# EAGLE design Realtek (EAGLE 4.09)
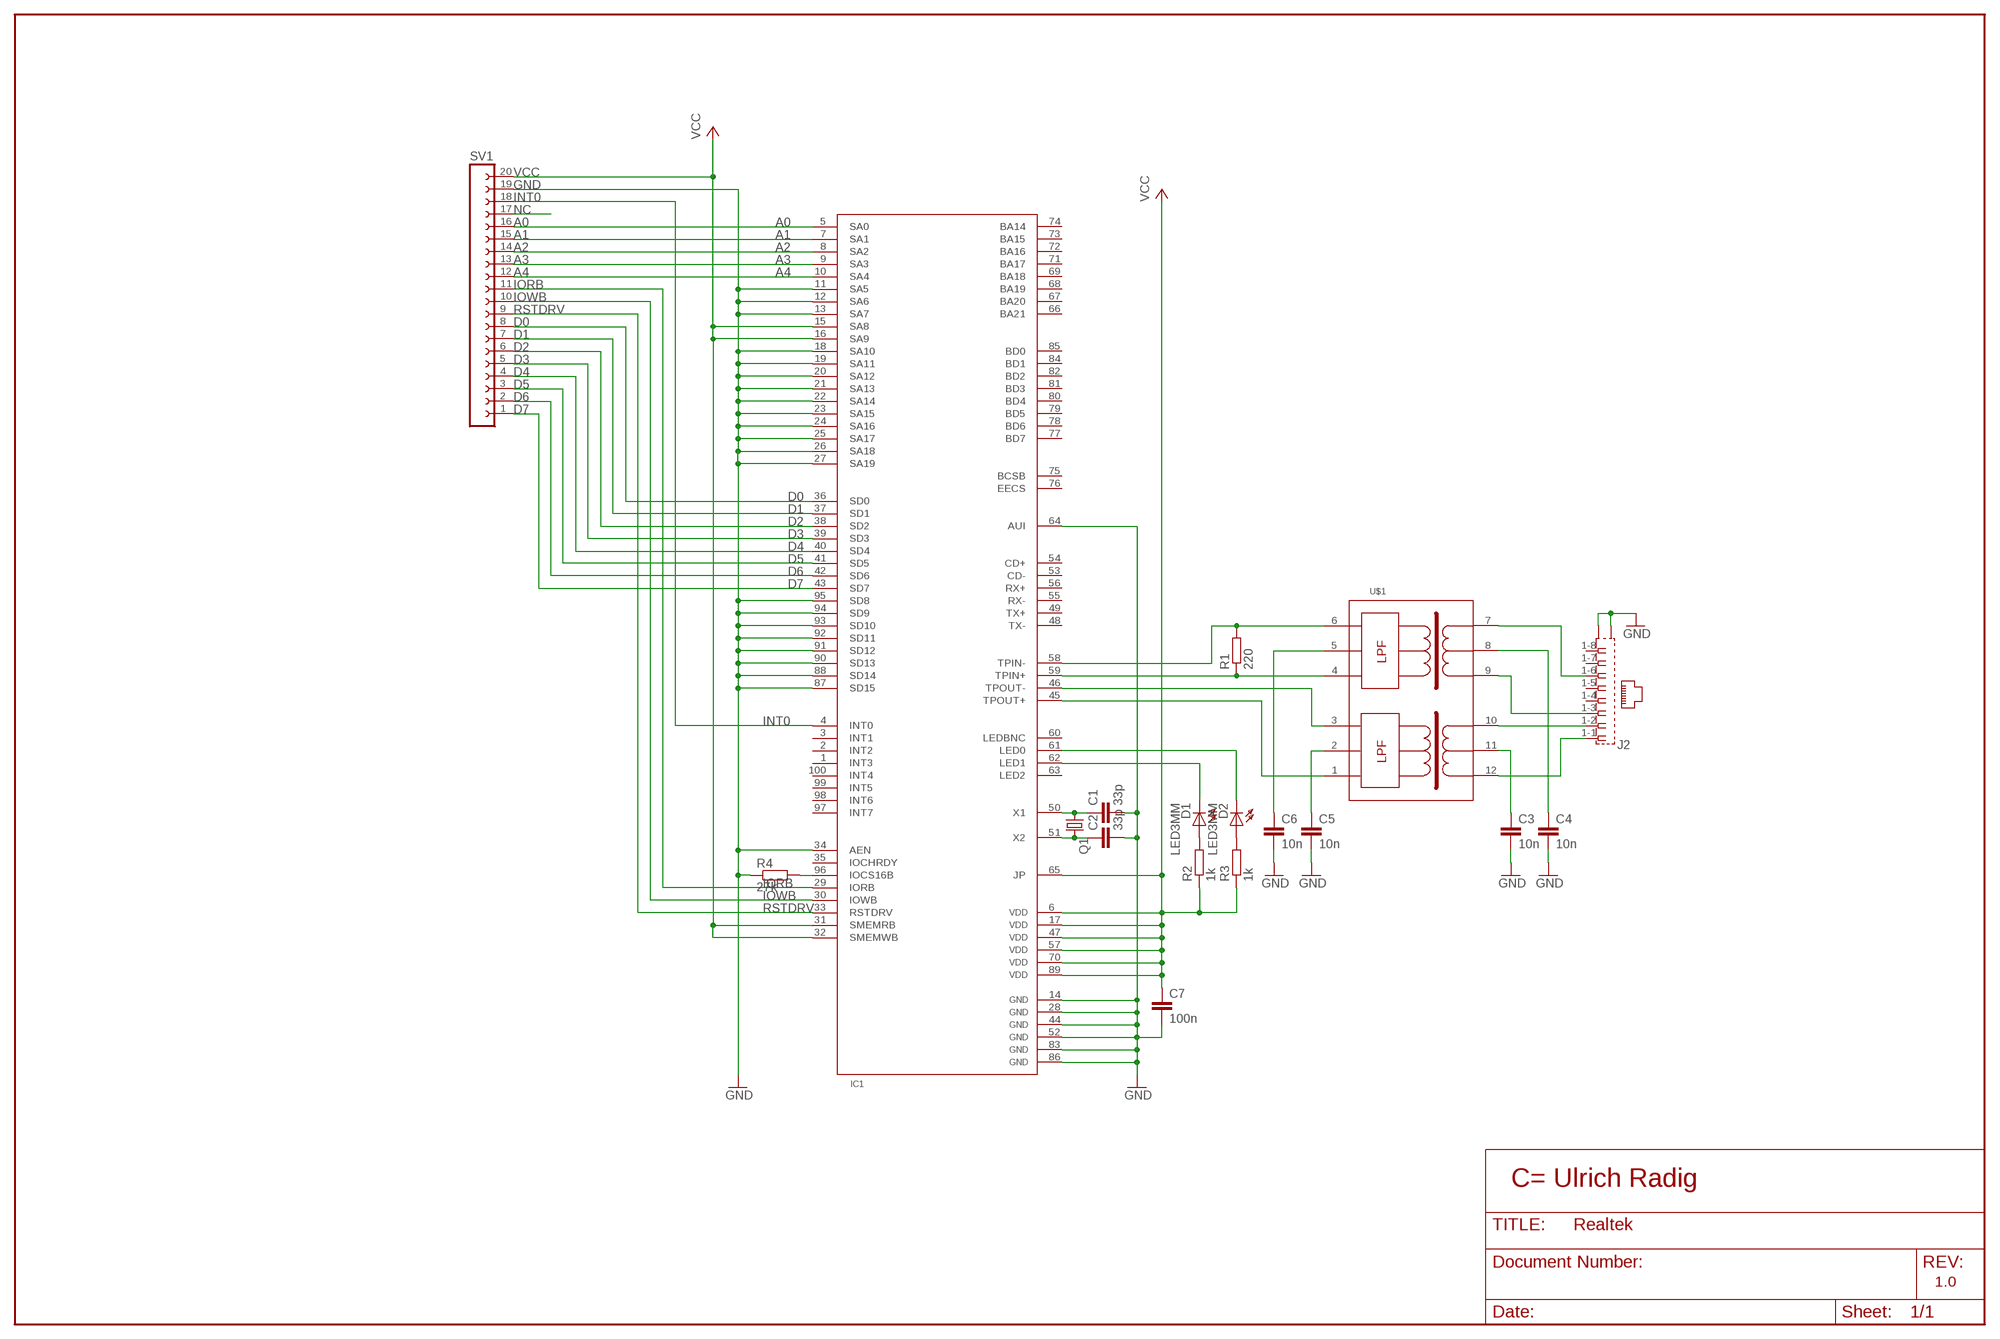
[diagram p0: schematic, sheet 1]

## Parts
C1  33p  C-EUC1206  [C1206]
C2  33p  C-EUC1206  [C1206]
C3  10n  C-EUC1206  [C1206]
C4  10n  C-EUC1206  [C1206]
C5  10n  C-EUC1206  [C1206]
C6  10n  C-EUC1206  [C1206]
C7  100n  C-EUC1206  [C1206]
D1  LED3MM  [LED3MM]
D2  LED3MM  [LED3MM]
IC1  RTL8019  [TQPF100]
J2  557786-1  [557786-1]
Q1  HC49U-H  [HC49U-H]
R1  220  R-EU_R1206  [R1206]
R2  1k  R-EU_M1206  [M1206]
R3  1k  R-EU_M1206  [M1206]
R4  27k  R-EU_M1206  [M1206]
SV1  FE20-1  [FE20]
U$1  20F001  [DIL16/12]

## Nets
A0: IC1.5(SA0) SV1.16
A1: IC1.7(SA1) SV1.15
A2: IC1.8(SA2) SV1.14
A3: IC1.9(SA3) SV1.13
A4: IC1.10(SA4) SV1.12
D0: IC1.36(SD0) SV1.8
D1: IC1.37(SD1) SV1.7
D2: IC1.38(SD2) SV1.6
D3: IC1.39(SD3) SV1.5
D4: IC1.40(SD4) SV1.4
D5: IC1.41(SD5) SV1.3
D6: IC1.42(SD6) SV1.2
D7: IC1.43(SD7) SV1.1
GND: C1.2 C2.2 C3.2 C4.2 C5.2 C6.2 C7.2 IC1.11(SA5) IC1.12(SA6) IC1.13(SA7) IC1.14(G1) IC1.18(SA10) IC1.19(SA11) IC1.20(SA12) IC1.21(SA13) IC1.22(SA14) IC1.23(SA15) IC1.24(SA16) IC1.25(SA17) IC1.26(SA18) IC1.27(SA19) IC1.28(G2) IC1.34(AEN) IC1.44(G3) IC1.52(G4) IC1.64(AUI) IC1.83(G5) IC1.86(G6) IC1.87(SD15) IC1.88(SD14) IC1.90(SD13) IC1.91(SD12) IC1.92(SD11) IC1.93(SD10) IC1.94(SD9) IC1.95(SD8) J2.G1(S2) J2.G2(S1) R4.1 SV1.19
INT0: IC1.4(INT0) SV1.18
IORB: IC1.29(IORB) SV1.11
IOWB: IC1.30(IOWB) SV1.10
N$1: J2.1-1 U$1.12
N$2: J2.1-2 U$1.10
N$3: D2.K(C) IC1.61(LED0)
N$4: D1.K(C) IC1.62(LED1)
N$5: D1.A R2.2
N$6: J2.1-3 U$1.9
N$7: J2.1-6 U$1.7
N$8: IC1.58(TPIN-) R1.2 U$1.6
N$9: IC1.59(TPIN+) R1.1 U$1.4
N$10: IC1.46(TPOUT-) U$1.3
N$11: IC1.45(TPOUT+) U$1.1
N$12: C5.1 U$1.2
N$13: C6.1 U$1.5
N$14: C1.1 IC1.50(X1) Q1.1
N$15: C2.1 IC1.51(X2) Q1.2
N$16: C3.1 U$1.11
N$17: C4.1 U$1.8
N$18: D2.A R3.2
N$31: IC1.96(IOCS16B) R4.2
NC: SV1.17
RSTDRV: IC1.33(RSTDRV) SV1.9
VCC: C7.1 IC1.6(V1) IC1.15(SA8) IC1.16(SA9) IC1.17(V2) IC1.31(SMEMRB) IC1.32(SMEMWB) IC1.47(V3) IC1.57(V4) IC1.65(JP) IC1.70(V5) IC1.89(V6) R2.1 R3.1 SV1.20
Unconnected: IC1.1(INT3) IC1.2(INT2) IC1.3(INT1) IC1.35(IOCHRDY) IC1.48(TX-) IC1.49(TX+) IC1.53(CD-) IC1.54(CD+) IC1.55(RX-) IC1.56(RX+) IC1.60(LEDBNC) IC1.63(LED2) IC1.66(BA21) IC1.67(BA20) IC1.68(BA19) IC1.69(BA18) IC1.71(BA17) IC1.72(BA16) IC1.73(BA15) IC1.74(BA14) IC1.75(BCSB) IC1.76(EECS) IC1.77(BD7) IC1.78(BD6) IC1.79(BD5) IC1.80(BD4) IC1.81(BD3) IC1.82(BD2) IC1.84(BD1) IC1.85(BD0) IC1.97(INT7) IC1.98(INT6) IC1.99(INT5) IC1.100(INT4) J2.1-4 J2.1-5 J2.1-7 J2.1-8

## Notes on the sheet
- C= Ulrich Radig
- 1.0

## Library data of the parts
C1-C7 = rcl:C-EU: CAPACITOR, European symbol
D1 D2 = led:LED3MM: LED
IC1 = Realtek:RTL8019
J2 = con-amp:557786-1: AMP CONNECTOR
Q1 = crystal:HC49U-H: CRYSTAL
R1-R4 = rcl:R-EU_: RESISTOR, European symbol
SV1 = con-lsta:FE20-1: FEMALE HEADER
U$1 = Realtek:20F001

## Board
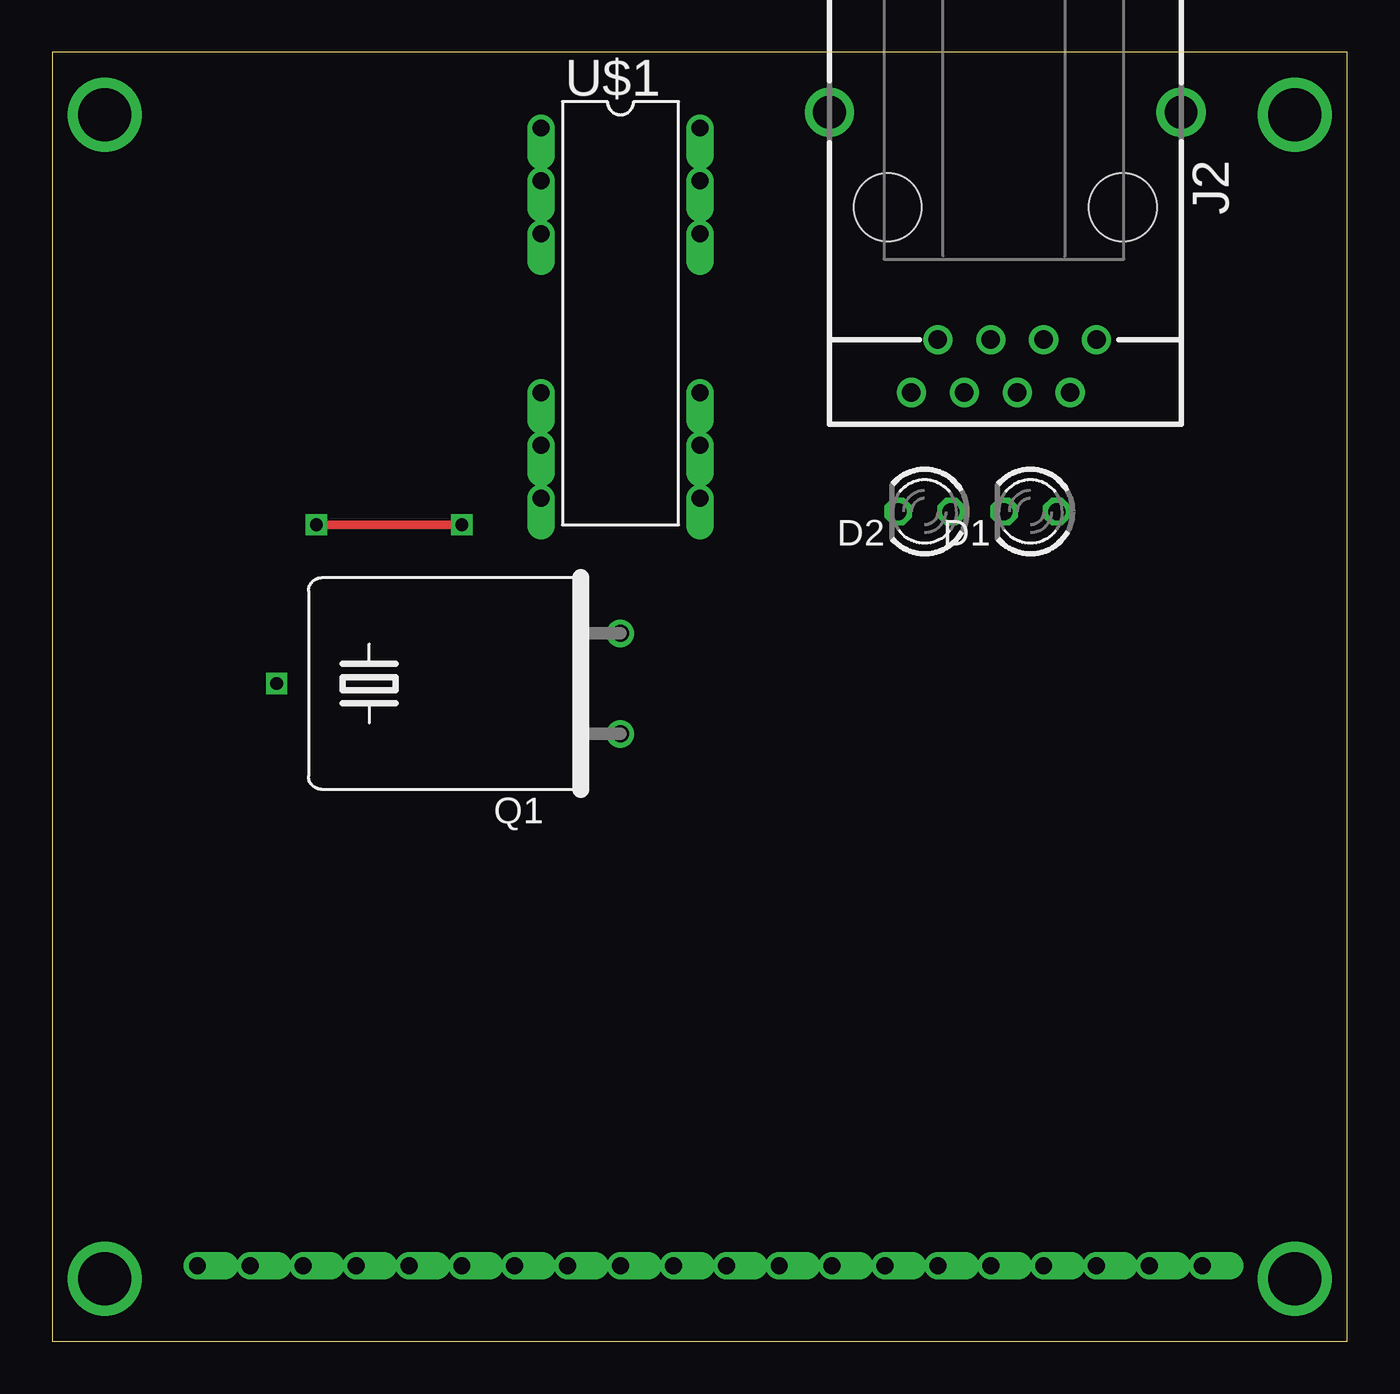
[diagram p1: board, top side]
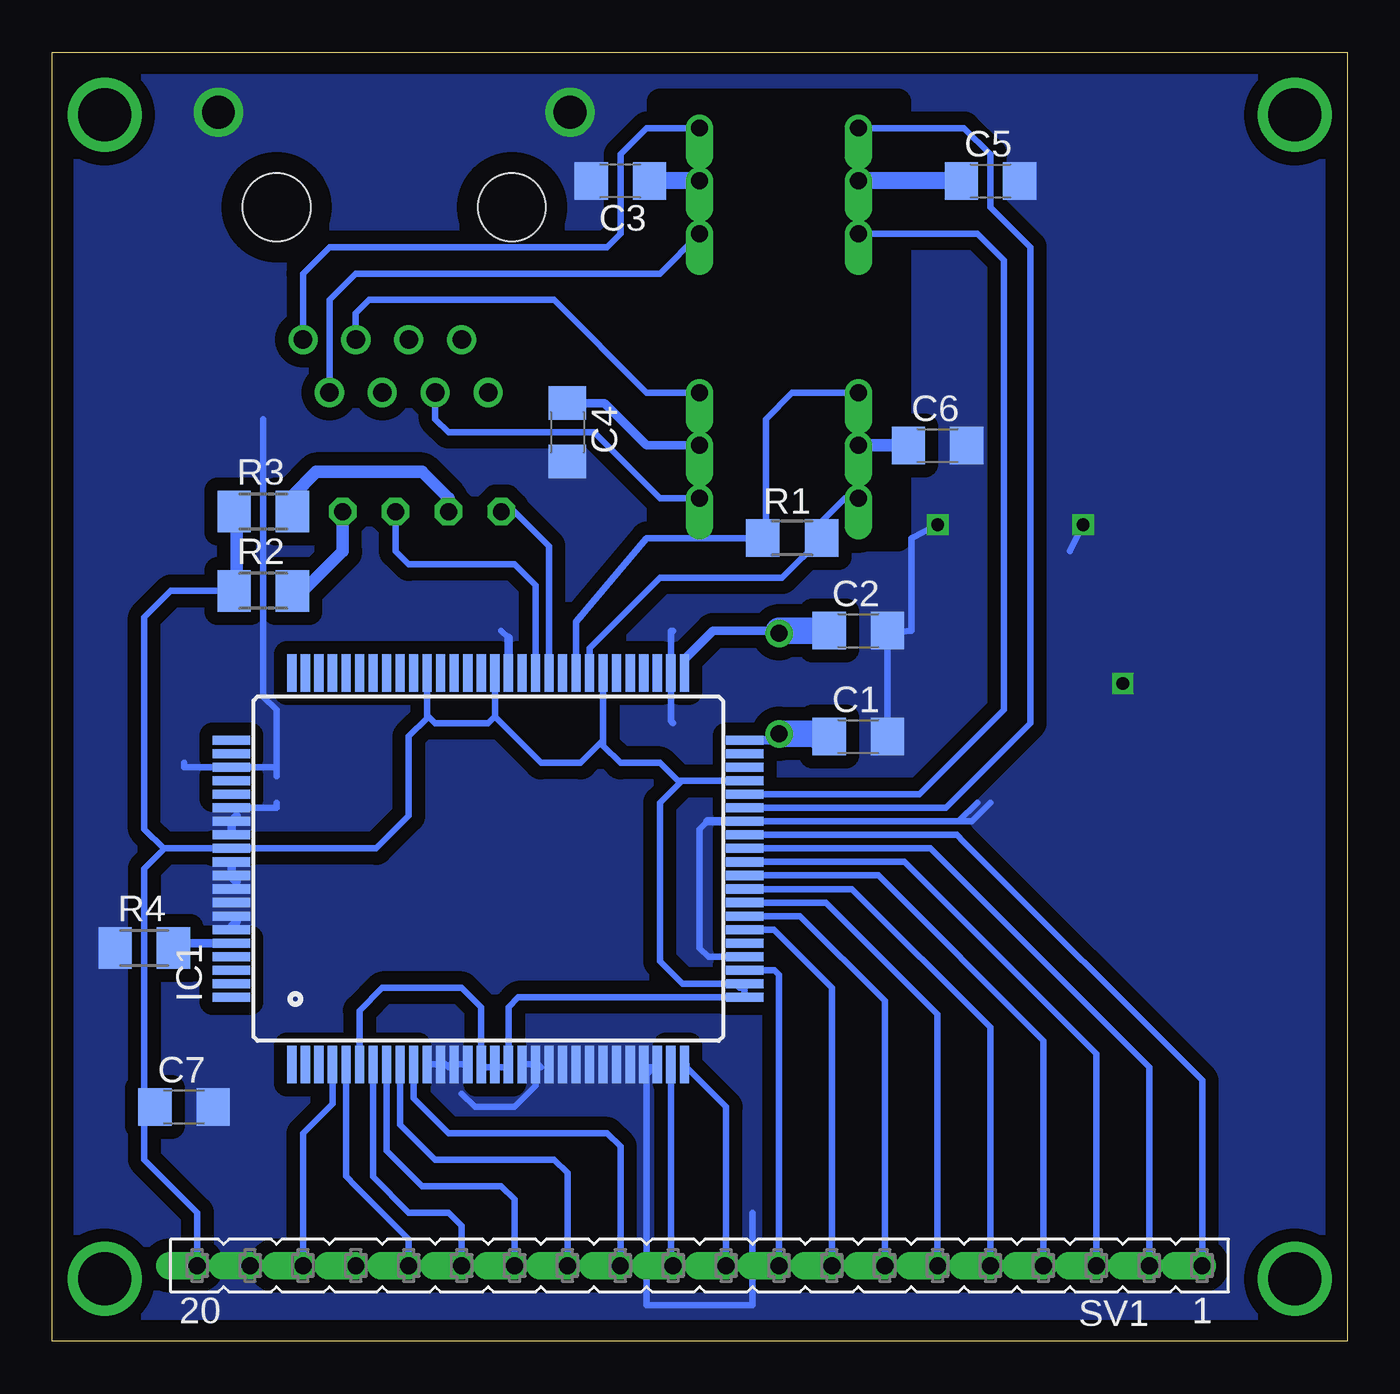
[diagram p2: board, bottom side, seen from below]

Size 62.21 x 61.9 mm. Coordinates in mm from the lower left corner, seen from the top.
Outline: 0,0 62.21,0 62.21,61.9 0,61.9 0,0
Copper layers used: Top, Bottom
bRestrict: area 21.6,38.6 to 33,59.5

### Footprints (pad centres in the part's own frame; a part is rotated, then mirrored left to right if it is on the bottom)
C1206 = smd 1.6 x 1.8: 1 -1.4,0; 2 1.4,0
LED3MM = drill 0.813 octagon: A -1.27,0; K 1.27,0
TQPF100 = smd 1.8 x 0.44: 1 -9.395,9.425; 2 -9.395,8.775; 3 -9.395,8.125; 4 -9.395,7.475; 5 -9.395,6.825; 6 -9.395,6.175; 7 -9.395,5.525; 8 -9.395,4.875; 9 -9.395,4.225; 10 -9.395,3.575; 11 -9.395,2.925; 12 -9.395,2.275; 13 -9.395,1.625; 14 -9.395,0.975; 15 -9.395,0.325; 16 -9.395,-0.325; 17 -9.395,-0.975; 18 -9.395,-1.625; 19 -9.395,-2.275; 20 -9.395,-2.925; 21 -9.395,-3.575; 22 -9.395,-4.225; 23 -9.395,-4.875; 24 -9.395,-5.525; 25 -9.395,-6.175; 26 -9.395,-6.825; 27 -9.395,-7.475; 28 -9.395,-8.125; 29 -9.395,-8.775; 30 -9.395,-9.425; 51 9.395,-9.425; 52 9.395,-8.775; 53 9.395,-8.125; 54 9.395,-7.475; 55 9.395,-6.825; 56 9.395,-6.175; 57 9.395,-5.525; 58 9.395,-4.875; 59 9.395,-4.225; 60 9.395,-3.575; 61 9.395,-2.925; 62 9.395,-2.275; 63 9.395,-1.625; 64 9.395,-0.975; 65 9.395,-0.325; 66 9.395,0.325; 67 9.395,0.975; 68 9.395,1.625; 69 9.395,2.275; 70 9.395,2.925; 71 9.395,3.575; 72 9.395,4.225; 73 9.395,4.875; 74 9.395,5.525; 75 9.395,6.175; 76 9.395,6.825; 77 9.395,7.475; 78 9.395,8.125; 79 9.395,8.775; 80 9.395,9.425 | smd 0.44 x 1.8: 31 -6.175,-12.32; 32 -5.525,-12.32; 33 -4.875,-12.32; 34 -4.225,-12.32; 35 -3.575,-12.32; 36 -2.925,-12.32; 37 -2.275,-12.32; 38 -1.625,-12.32; 39 -0.975,-12.32; 40 -0.325,-12.32; 41 0.325,-12.32; 42 0.975,-12.32; 43 1.625,-12.32; 44 2.275,-12.32; 45 2.925,-12.32; 46 3.575,-12.32; 47 4.225,-12.32; 48 4.875,-12.32; 49 5.525,-12.32; 50 6.175,-12.32; 81 6.175,12.32; 82 5.525,12.32; 83 4.875,12.32; 84 4.225,12.32; 85 3.575,12.32; 86 2.925,12.32; 87 2.275,12.32; 88 1.625,12.32; 89 0.975,12.32; 90 0.325,12.32; 91 -0.325,12.32; 92 -0.975,12.32; 93 -1.625,12.32; 94 -2.275,12.32; 95 -2.925,12.32; 96 -3.575,12.32; 97 -4.225,12.32; 98 -4.875,12.32; 99 -5.525,12.32; 100 -6.175,12.32
557786-1 = drill 0.889 round: 1-1 -4.445,6.35; 1-2 -3.175,8.89; 1-3 -1.905,6.35; 1-4 -0.635,8.89; 1-5 0.635,6.35; 1-6 1.905,8.89; 1-7 3.175,6.35; 1-8 4.445,8.89 | drill 1.575 pad 2.184 round: G1 -8.509,-4.572; G2 8.382,-4.572 | hole 3.251: -5.715,0; 5.588,0
HC49U-H = drill 0.813 round: 1 -2.413,-5.08; 2 2.413,-5.08
R1206 = smd 1.6 x 1.803: 1 -1.422,0; 2 1.422,0
M1206 = smd 1.6 x 2: 1 -1.4,0; 2 1.4,0
FE20 = drill 0.813 offset: 1 -24.13,0; 2 -21.59,0; 3 -19.05,0; 4 -16.51,0; 5 -13.97,0; 6 -11.43,0; 7 -8.89,0; 8 -6.35,0; 9 -3.81,0; 10 -1.27,0; 11 1.27,0; 12 3.81,0; 13 6.35,0; 14 8.89,0; 15 11.43,0; 16 13.97,0; 17 16.51,0; 18 19.05,0; 19 21.59,0; 20 24.13,0
DIL16/12 = drill 0.813 offset: 1 -8.89,-3.81; 2 -6.35,-3.81; 3 -3.81,-3.81; 4 3.81,-3.81; 5 6.35,-3.81; 6 8.89,-3.81; 7 8.89,3.81; 8 6.35,3.81; 9 3.81,3.81; 10 -3.81,3.81; 11 -6.35,3.81; 12 -8.89,3.81

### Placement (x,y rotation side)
C1  23.49,29.04 0 bottom
C2  23.49,34.12 0 bottom
C3  34.92,55.72 180 bottom
C4  37.46,43.65 270 bottom
C5  17.14,55.72 0 bottom
C6  19.68,43.02 0 bottom
C7  55.88,11.26 0 bottom
D1  46.99,39.84 180 top
D2  41.91,39.84 180 top
IC1  41.27,22.7 90 bottom
J2  45.72,54.45 180 top
Q1  22.22,31.58 90 top
R1  26.66,38.57 0 bottom
R2  52.07,36.03 0 bottom
R3  52.07,39.84 0 bottom
R4  57.78,18.88 0 bottom
SV1  31.11,3.65 180 bottom
U$1  27.3,49.37 270 top

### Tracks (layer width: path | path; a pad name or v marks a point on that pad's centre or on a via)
A0
  Bottom 0.305: SV1.16 45.08,4.92 47.62,7.46 48.1,7.93 IC1.5
A1
  Bottom 0.305: SV1.15 42.54,5.55 43.18,6.19 45.08,6.19 46.8,7.9 IC1.7
A2
  Bottom 0.305: SV1.14 40,6.82 40.64,7.46 44.45,7.46 46.15,9.15 IC1.8
A3
  Bottom 0.305: SV1.13 37.46,8.09 38.1,8.72 43.81,8.72 45.5,10.41 IC1.9
A4
  Bottom 0.305: SV1.12 34.92,9.36 35.56,9.99 43.18,9.99 44.85,11.66 IC1.10
D0
  Bottom 0.305: IC1.36 27.55,19.77 24.76,16.98 SV1.8
D1
  Bottom 0.305: IC1.37 26.29,20.42 22.22,16.34 SV1.7
D2
  Bottom 0.305: IC1.38 25.04,21.07 19.68,15.71 SV1.6
D3
  Bottom 0.305: IC1.39 23.79,21.72 17.14,15.07 SV1.5
D4
  Bottom 0.305: IC1.40 22.53,22.37 14.6,14.44 SV1.4
D5
  Bottom 0.305: IC1.41 21.27,23.02 12.06,13.8 SV1.3
D6
  Bottom 0.305: SV1.2 9.52,13.17 19.68,23.33 20.02,23.67 IC1.42
D7
  Bottom 0.305: SV1.1 6.98,12.54 18.41,23.96 18.77,24.32 IC1.43
GND  (via drill 0.61)
  Top 0.406: v19.68,39.21 v12.7,39.21
  Bottom 0.305: C1.2 22.09,34 20.95,34.12 20.95,38.57 v19.68,39.21 | v12.7,39.21 13.33,37.94 | IC1.27 33.67,13.17 33.28,13.17 IC1.28 33.65,12.79 33.65,1.74 28.57,1.74 28.57,6.19 | 18.68,24.97 IC1.44 | 18.68,24.97 17.77,25.87 | 42.54,11.9 41.91,11.26 40,11.26 39,12.27 IC1.19 38.86,13.3 | 38.86,13.3 IC1.18 | 38.86,13.3 38.73,13.17 | IC1.13 43.05,13.3 | 43.05,13.3 IC1.14 | 43.05,13.3 43.18,13.17 43.31,13.3 | 43.31,13.3 IC1.12 | 43.31,13.3 IC1.11 | IC1.86 51.43,25.62 51.43,25.87 | 18.68,24.97 18.04,24.97 17.14,25.87 | IC1.34 30.69,18.47 31.11,18.88 31.11,24.6 30.74,24.97 | 51.43,27.57 51.43,27.14 | 51.43,27.57 51.43,30.31 52.07,30.95 52.07,44.29 | 32.38,29.68 32.5,29.79 32.5,34.12 32.38,34.12 32.5,34.01 IC1.52 | 40.3,33.79 40.64,34.12 | IC1.83 55.88,27.57 | 55.88,27.57 51.43,27.57 | 55.88,27.57 55.88,27.77
  Bottom 0.406: IC1.44 30.74,24.97 | IC1.64 40.3,33.79 | IC1.87 | IC1.88 IC1.87 | IC1.87 53.34,25.23 | 53.59,22.31 IC1.91 | IC1.90 53.59,22.31 | 53.59,22.31 53.34,22.06 | IC1.94 53.34,20.15 53.59,19.9 IC1.95
  other vias: 10.79,31.58
  pour Bottom (isolate 0.635, no thermals): 1.26,60.8 1.26,0.47 62.23,0.47 62.23,60.8
INT0
  Bottom 0.305: IC1.4 48.75,11.41 50.16,9.99 SV1.18
IORB
  Bottom 0.305: IC1.29 32.5,3.76 SV1.11
IOWB
  Bottom 0.305: 31.75,13.17 29.84,11.26 SV1.10 | 31.75,13.17 31.85,13.27 31.75,13.27 31.75,13.17 | 31.75,13.17 31.75,13.3 IC1.30
N$1
  Bottom 0.305: J2.1-1 50.16,51.27 48.89,52.54 35.56,52.54 34.92,53.18 34.92,56.98 33.65,58.26 U$1.12
N$2
  Bottom 0.305: U$1.10 33.02,51.27 47.62,51.27 48.89,50 J2.1-2
N$3
  Bottom 0.305: D2.K 40,39.84 38.35,38.19 IC1.61
N$4
  Bottom 0.305: D1.K 45.72,37.94 45.08,37.3 40,37.3 39,36.3 IC1.62
N$5
  Bottom 0.305: 50.8,36.03 R2.2 50.16,36.03
  Bottom 0.61: 50.16,36.03 48.26,37.94 D1.A
N$6
  Bottom 0.305: U$1.9 33.65,45.55 38.1,50 46.99,50 47.62,49.37 J2.1-3
N$7
  Bottom 0.305: U$1.7 33.02,40.48 36.19,43.65 43.18,43.65 43.81,44.29 J2.1-6
N$8
  Bottom 0.305: U$1.6 24.12,40.48 25.39,39.21 25.39,38.57 R1.2 27.15,36.67 33.02,36.67 36.4,33.29 IC1.58
N$9
  Bottom 0.305: 37.05,34.54 33.65,38.57 R1.1 27.93,38.57 27.93,44.29 26.66,45.55 U$1.4 | 37.05,34.54 IC1.59 | 37.05,34.54 36.83,34.76
N$10
  Bottom 0.305: U$1.3 17.77,53.18 16.5,51.91 16.5,30.31 20.55,26.27 IC1.46
N$11
  Bottom 0.305: U$1.1 18.41,58.26 17.14,56.98 17.14,54.45 15.23,52.54 15.23,29.68 19.29,25.62 IC1.45
N$12
  Bottom 0.813: C5.1 U$1.2
N$13
  Bottom 0.61: 20.95,43.02 C6.1 U$1.5
N$14
  Bottom 0.305: Q1.1 26.03,29.04 | 26.03,29.04 26.03,28.87 | 26.03,29.04 26.2,28.87
  Bottom 0.406: 26.2,28.87 IC1.50
  Bottom 1.27: C1.1 25.39,29.04 25.52,29.17 Q1.1
N$15
  Bottom 0.305: 27.3,34.12 Q1.2 | 31.85,32.76 IC1.51
  Bottom 0.406: 31.85,32.76 30.47,34.12 27.3,34.12
  Bottom 1.27: C2.1 27.3,34.12
N$16
  Bottom 0.813: 33.65,55.72 C3.1 U$1.11
N$17
  Bottom 0.406: U$1.8 33.65,43.02 35.69,45.05 C4.1
N$18
  Bottom 0.305: 50.67,40.61 R3.2
  Bottom 0.61: D2.A 43.18,40.48 44.45,41.75 49.53,41.75 50.67,40.61
N$19  (via drill 2.54)
  other vias: 2.54,58.89
N$20  (via drill 2.54)
  other vias: 2.54,3.01
N$21  (via drill 2.54)
  other vias: 59.69,3.01
N$22  (via drill 2.54)
  other vias: 59.69,58.89
N$31
  Bottom 0.406: R4.2 55.88,18.88 55.64,19.12 IC1.96
RSTDRV
  Bottom 0.305: IC1.33 27.5,17.82 27.3,17.61 SV1.9
VCC
  Bottom 0.305: SV1.20 55.24,6.19 57.78,8.72 57.78,11.26 | 57.78,11.26 57.78,22.7 56.85,23.62 | 56.51,36.03 R2.1 53.34,36.03 56.51,36.03 | 53.34,39.71 R3.1 | 56.85,23.62 56.85,23.67 57.78,24.6 57.78,34.76 56.51,36.03 | 56.85,23.62 56.81,23.67 IC1.89 46.65,23.67 45.08,25.23 45.08,29.04 44.2,29.93 IC1.70 44.2,30.06 43.81,29.68 41.27,29.68 40.95,30 IC1.65 40.95,29.99 38.73,27.77 36.83,27.77 35.75,28.86 IC1.57 35.75,28.6 34.92,27.77 33.02,27.77 32.16,26.92 31.96,26.92 | IC1.6 47.45,15.88 46.35,16.98 42.54,16.98 41.6,16.04 IC1.15 41.47,13.17 41.08,13.17 IC1.16 40.82,13.17 40.43,13.17 IC1.17 40.3,16.05 39.83,16.52 IC1.31 28.95,16.98 | 31.96,26.92 IC1.47 | 31.96,26.92 33.02,25.87 33.02,18.25 31.93,17.17 IC1.32 28.95,16.98 | 28.95,16.98 29.2,16.98 | 57.78,11.26 C7.1
  Bottom 0.61: 53.34,36.03 53.34,39.71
